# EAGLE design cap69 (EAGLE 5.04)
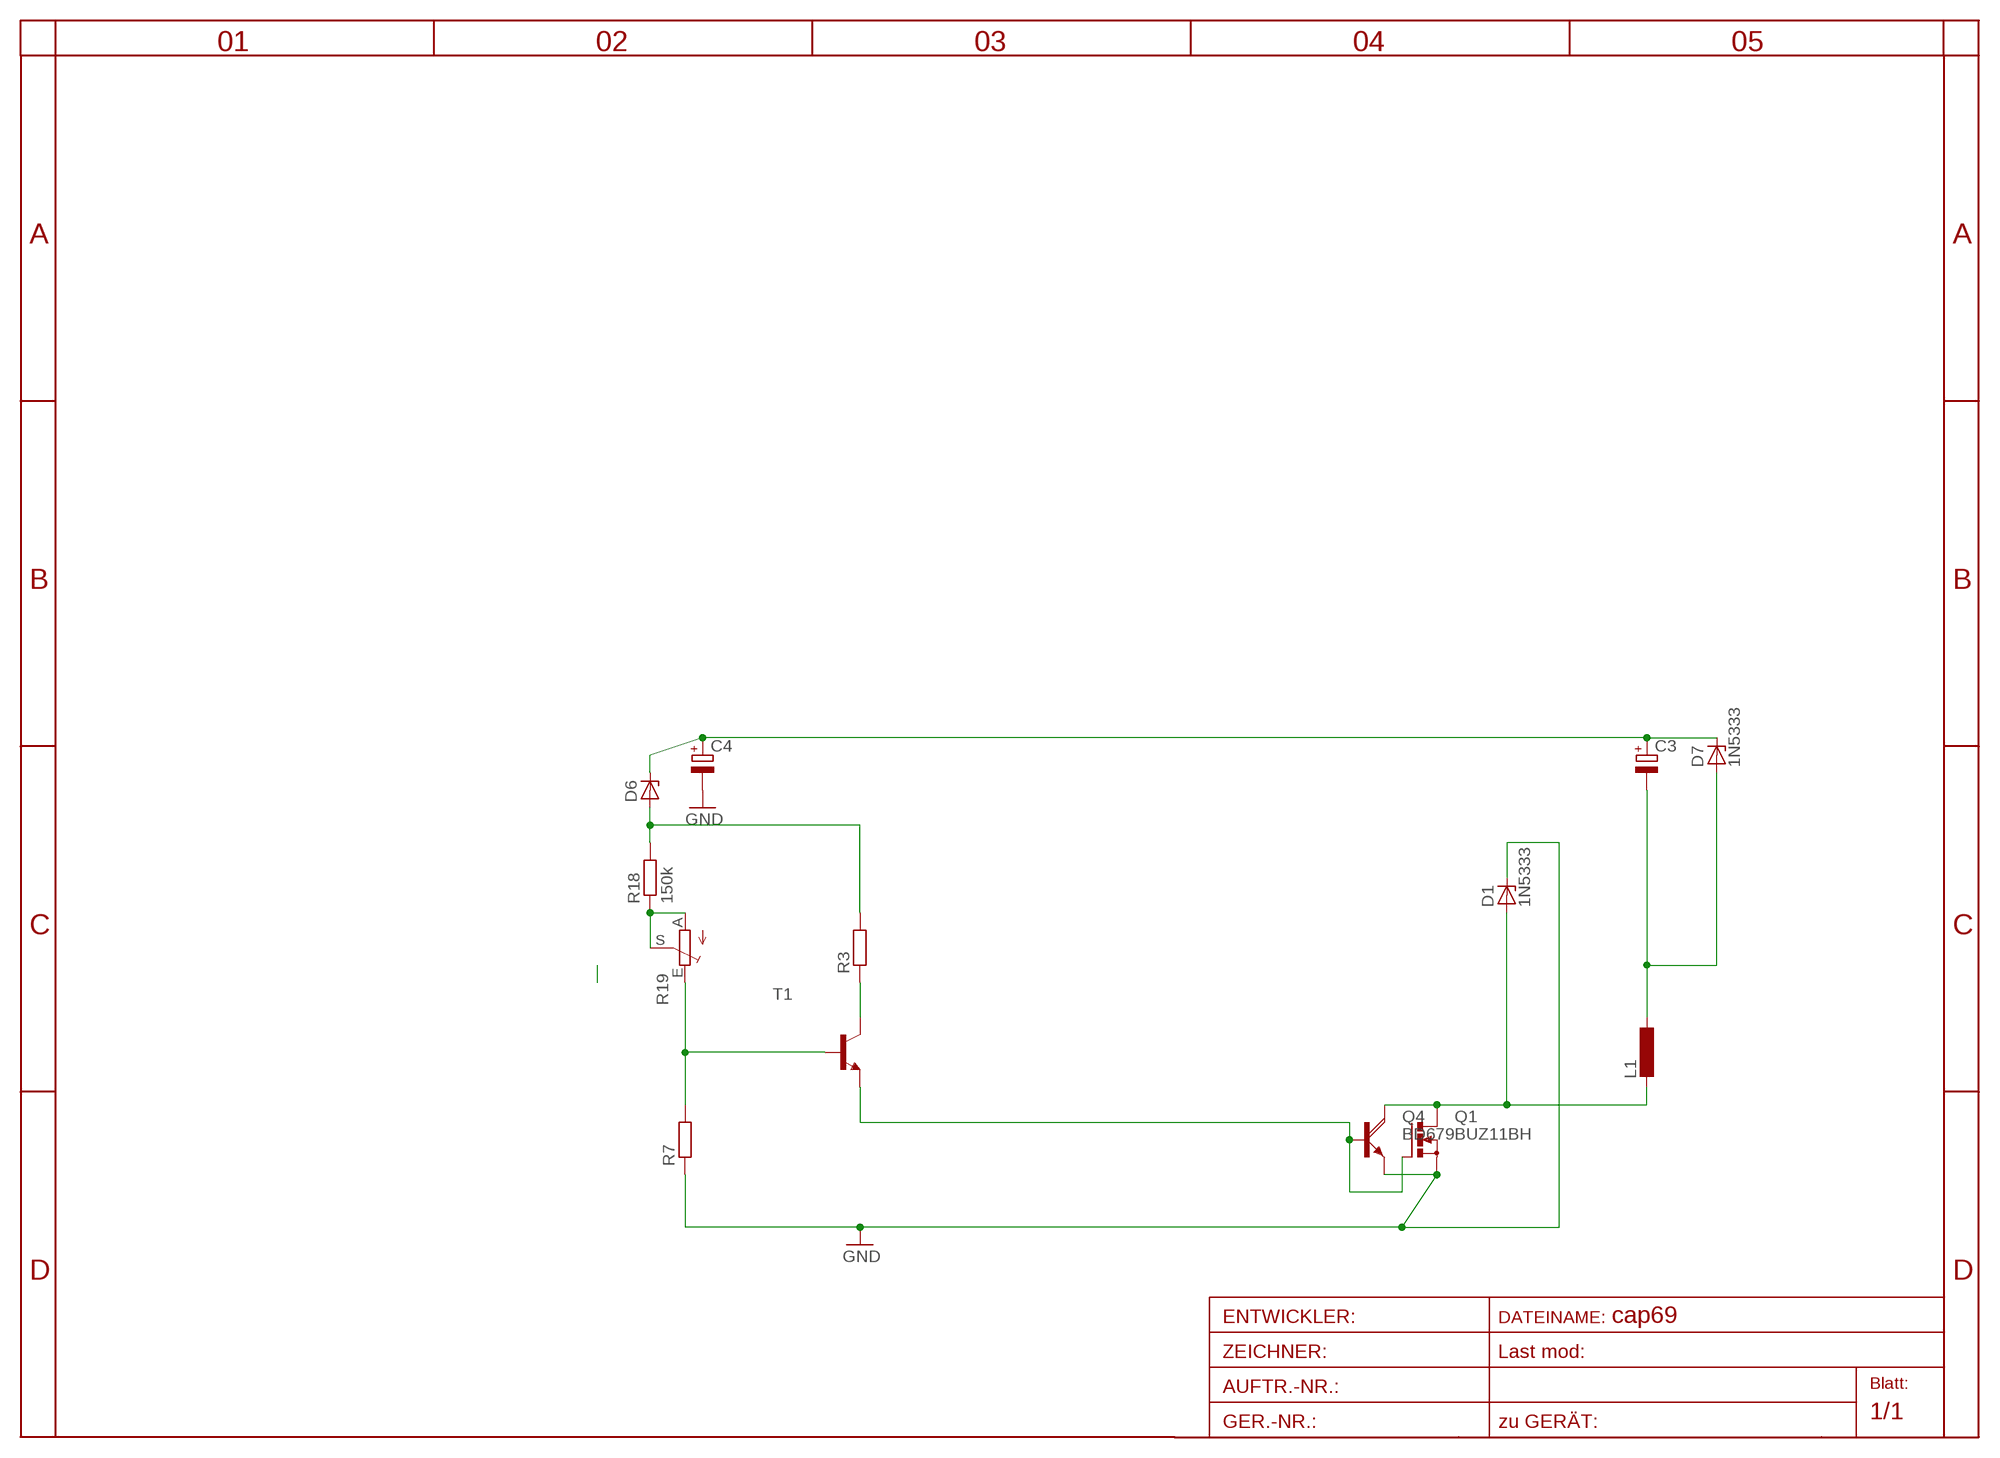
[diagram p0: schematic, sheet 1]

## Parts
C3  CPOL-EUE5-8.5  [E5-8,5]
C4  CPOL-EUE5-8.5  [E5-8,5]
D1  1N5333  [C1702-15]
D6  ZENER-DIODESMB  [SMB]
D7  1N5333  [C1702-15]
L1  L-EU2200-15.24  [2200-15.24]
Q1  BUZ11BH  [TO220BH]
Q4  BD679  [TO126AV]
R3  R-EU_R0805  [R0805]
R7  R-EU_R0805  [R0805]
R18  150k  R-EU_R1206  [R1206]
R19  TRIM_EU-CA6V  [CA6V]
T1  BC846BLT1-NPN-SOT23-BEC  [SOT23-BEC]

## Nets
GND: C4.- D1.C Q1.S Q4.E R7.1
HOTSPOT: D1.A L1.2 Q1.D Q4.C
N$3: Q1.G Q4.B T1.E
N$6: R7.2 R19.E T1.B
N$9: R3.1 T1.C
N$13: R18.1 R19.A R19.S
N$23: D6.A R3.2 R18.2
V60: C3.+ C4.+ D6.C D7.C
VOUT: C3.- D7.A L1.1

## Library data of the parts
C3 C4 = rcl:CPOL-EU: POLARIZED CAPACITOR, European symbol
D1 D7 = diode-1:1N5333: Z DIODE
D6 = diode-1:ZENER-DIODE: Z-Diode
L1 = rcl:L-EU: INDUCTOR, European symbol
Q1 = transistor-power:BUZ11: N-CHANNEL MOS FET
Q4 = transistor-power:BD679: NPN DARLINGTON TRANSISTOR
R3 = rcl:R-EU_: RESISTOR, European symbol
R7 R18 = rcl-2:R-EU_: RESISTOR, European symbol
R19 = pot:TRIM_EU-: POTENTIOMETER
T1 = transistor-neu-to92:*-NPN-: NPN Transistror

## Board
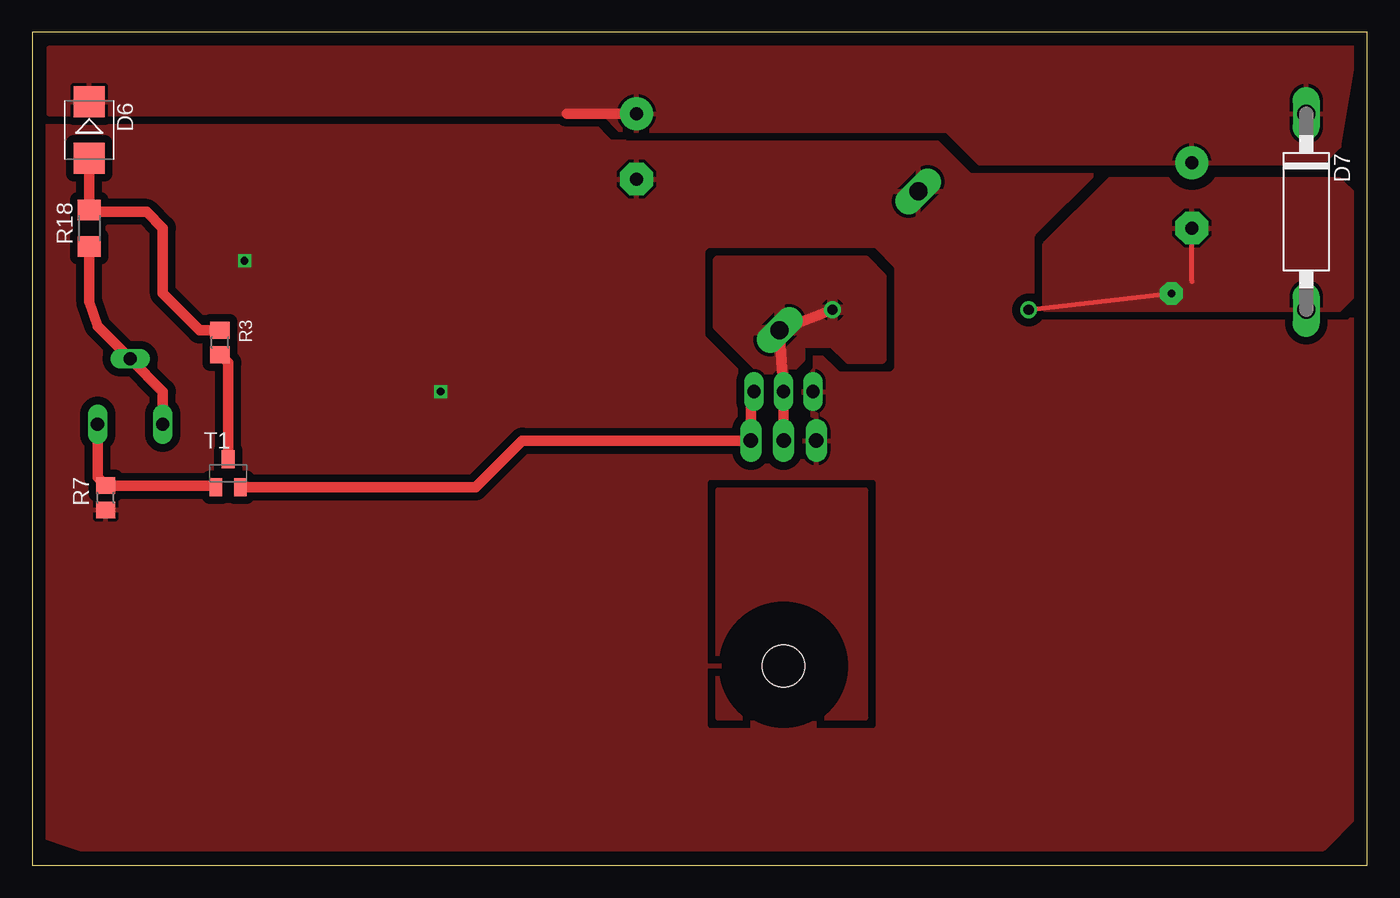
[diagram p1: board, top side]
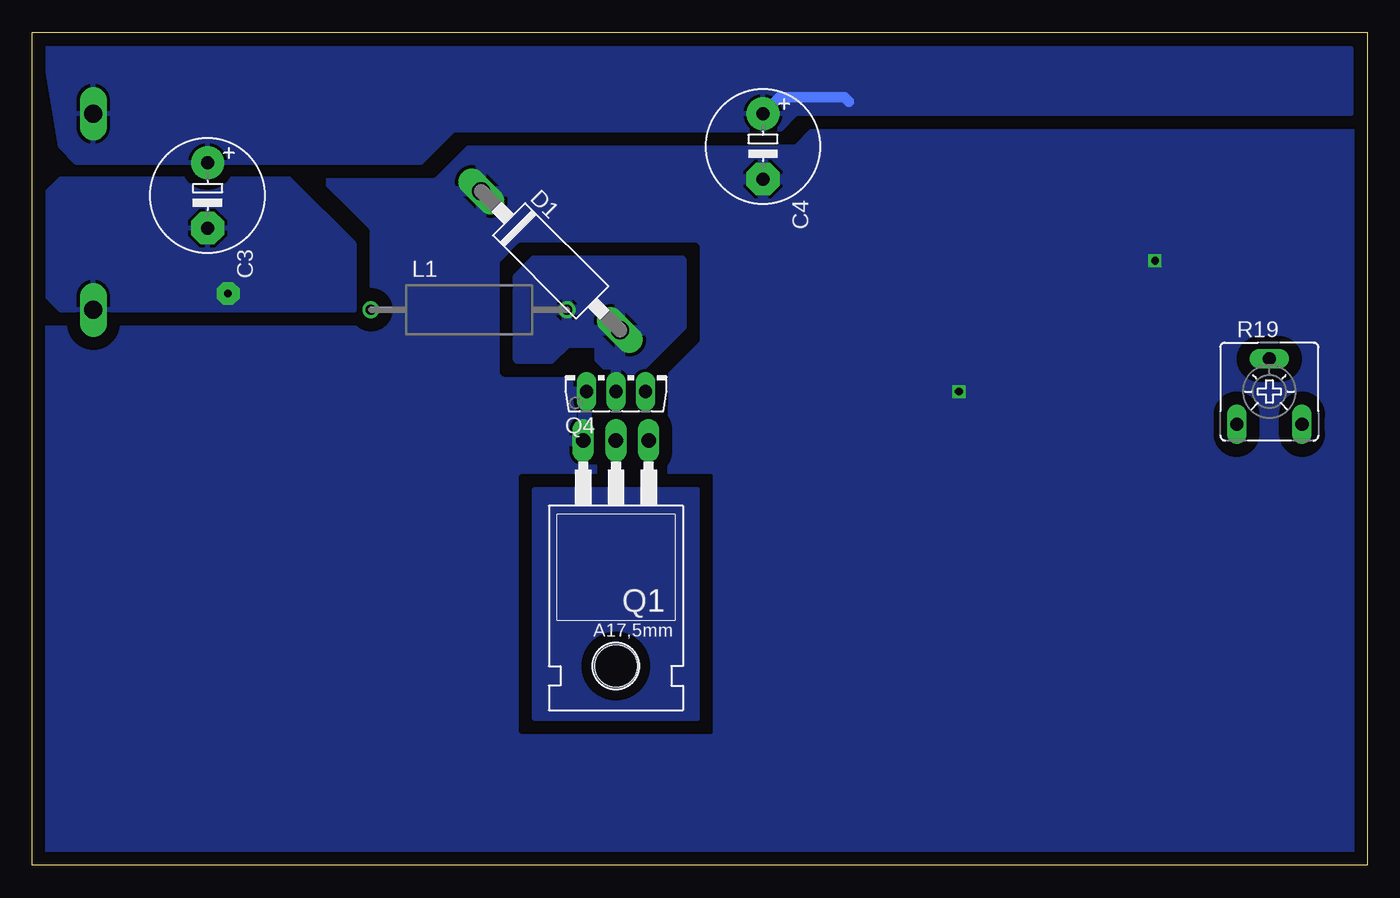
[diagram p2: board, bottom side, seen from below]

Size 103.81 x 64.76 mm. Coordinates in mm from the lower left corner, seen from the top.
Outline: 0,0 103.81,0 103.81,64.76 0,64.76 0,0
Copper layers (1*16): Top 0.035mm / dielectric 1.5mm / Bottom 0.035mm
Design rules "default": minimum track width 10mil, minimum drill 24mil, track to track 8mil, track to pad 8mil, pad to pad 8mil, via to via 8mil, smd to smd 8mil, copper to edge 40mil, drill to drill 8mil, minimum pad ring 10mil, minimum via ring 8mil, stop-mask expansion 4mil, vias tented up to drill 0mil, thermal gap 10mil

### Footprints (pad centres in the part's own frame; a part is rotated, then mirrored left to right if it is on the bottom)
E5-8,5 = drill 1.016 pad 2.54 round: + -2.54,0 | drill 1.016 pad 2.54 octagon: - 2.54,0
C1702-15 = drill 1.397 long: A 7.62,0; C -7.62,0
SMB = smd 2.4 x 2.4: A 2.2,0; C -2.2,0
2200-15.24 = drill 0.8 pad 1.27 round: 1 -7.62,0; 2 7.62,0
TO220BH = drill 1.118 long: D 0,-6.35; G -2.54,-6.35; S 2.54,-6.35 | hole 3.302: 0,11.176
TO126AV = drill 1.016 long: B 2.286,-1.27; C 0,-1.27; E -2.286,-1.27
R0805 = smd 1.3 x 1.5: 1 -0.95,0; 2 0.95,0
R1206 = smd 1.6 x 1.803: 1 -1.422,0; 2 1.422,0
CA6V = drill 1.016 long: A -2.54,-2.54; E 2.54,-2.54; S 0,2.54
SOT23-BEC = smd 1 x 1.4: B -0.95,-1.1; C 0,1.1; E 0.95,-1.1

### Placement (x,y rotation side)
C3  90.17,52.07 270 bottom
C4  46.99,55.88 270 bottom
D1  63.5,46.99 315 bottom
D6  4.45,57.15 270 top
D7  99.06,50.8 270 top
L1  69.85,43.18 0 bottom
Q1  58.42,26.67 180 bottom
Q4  58.42,38.1 0 bottom
R3  14.61,40.64 90 top
R7  5.71,28.57 90 top
R18  4.45,49.53 90 top
R19  7.62,36.83 0 bottom
T1  15.24,30.48 0 top

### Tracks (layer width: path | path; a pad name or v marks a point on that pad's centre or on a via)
GND  (via drill 0.6)
  other vias: 16.51,46.99 31.75,36.83
  pour Bottom (isolate 1.016, rank 5): 102.87,60.96 102.87,0 90.17,0 1.27,1.27 1.27,53.34 1.27,58.42
  pour Top (isolate 0.61, rank 5): 1.27,63.5 99.06,63.5 102.87,59.69 102.87,3.81 100.33,1.27 3.81,1.27 0,2.54
HOTSPOT
  Top 0.813: L1.2 D1.A Q4.C Q1.D
  pour Top: 53.34,46.99 64.77,46.99 66.04,45.72 66.04,39.37 63.5,39.37 62.23,40.64 59.69,40.64 59.69,39.37 58.42,38.1 57.15,38.1 53.34,41.91
  pour Bottom: 53.34,46.99 64.77,46.99 66.04,45.72 66.04,39.37 63.5,39.37 62.23,40.64 59.69,40.64 59.69,39.37 58.42,38.1 57.15,38.1 53.34,41.91
N$3
  Top 0.406: 55.88,36.58 Q4.B
  Top 0.813: 55.88,36.58 Q1.G 38.1,33.02 34.46,29.38 T1.E
N$6
  Top 0.813: R19.E 5.08,30.16 R7.2 14.14,29.52 T1.B
N$9
  Top 0.813: T1.C 15.24,39.05 R3.1
N$13
  Top 0.813: R18.1 4.45,43.81 5.08,41.91 R19.S 10.16,36.83 R19.A
N$20
  pour Top (isolate 0.813, rank 3): 53.34,29.21 64.77,29.21 64.77,11.43 53.34,11.43
  pour Bottom (isolate 0.813, rank 3): 52.07,29.21 64.77,29.21 64.77,11.43 52.07,11.43
N$23
  Top 0.813: D6.A R18.2 4.6,50.8 8.89,50.8 10.16,49.53 10.16,44.45 13.02,41.59 R3.2
V60
  Top 0.813: C4.+ 41.57,58.42
  Bottom 0.813: 40.3,59.35 40.64,59.69 45.72,59.69 C4.+
  pour Top (isolate 0.813, rank 4): 102.87,63.5 1.27,63.5 1.27,58.42 44.45,58.42 45.72,57.15 71.12,57.15 73.66,54.61 100.33,54.61 101.6,55.88
  pour Bottom (isolate 0.813, rank 4): 102.87,63.5 1.27,63.5 1.27,58.42 7.62,58.42 44.45,58.42 45.72,57.15 71.12,57.15 73.66,54.61 100.33,54.61 101.6,55.88
VOUT  (via drill 0.6 pad 1.78)
  Top 0.406: L1.1 v88.58,44.45 | 90.17,45.4 C3.-
  pour Top (isolate 0.813, rank 3): 101.6,53.34 102.87,52.07 102.87,44.45 101.6,43.18 78.74,43.18 78.74,48.26 83.82,53.34
  pour Bottom (isolate 0.813, rank 3): 101.6,53.34 102.87,52.07 102.87,44.45 101.6,43.18 78.74,43.18 78.74,48.26 83.82,53.34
